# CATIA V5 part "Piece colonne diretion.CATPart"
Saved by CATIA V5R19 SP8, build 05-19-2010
Part number: Piece colonne diretion
Bounding box of the stored display mesh (mm): x -5.46 to 50.226, y -5.348 to 77.931, z -10 to 10
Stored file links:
  G:\EU_thinkMotion\CFAO_2010\MMS_groupe3\MMS_groupe3\A reprendre\lpastor\lpastor\Piece colonne diretion.CATPart
  C:\Users\Loïc\Documents\IFMA\Cours 2A\CFAO\Thinkmotion\Fourche avant.CATProduct
  G:\EU_thinkMotion\CFAO_2010\MMS_groupe3\MMS_groupe3\A reprendre\lpastor\lpastor\Pieces.CATProduct
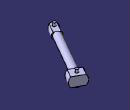
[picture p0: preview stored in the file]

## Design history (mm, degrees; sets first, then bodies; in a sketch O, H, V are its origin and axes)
External parameters (linked from other documents)
  External.Parametre_rayon_interieur_tube_cadre = 0.0045
Set1
  Plane1: linked copy from another document
  Line1 "Droite AB (colonne direction)": linked copy from another document
  Plane2 to Plane4: linked copy from another document
  Line2 "Droite B (colonne direction)": linked copy from another document
  Line3 "Droite A (colonne direction)": linked copy from another document
Body1 (main body)
  Sketch1 on Plane1, origin (36.0149, 62.7953, 0), H (0.8675, -0.4975, 0), V (0, 0, 1)
    circle A1 centre (0, 0) radius 4.5
    point P1 (0, 0)
    reference projected point E1 (0, 0) from Line1
    radius A1 = 4.5 {= External.Parametre_rayon_interieur_tube_cadre}
    coincidence: P1 E1
  Pad1: profile Sketch1, direction (-0.4975, -0.8675, 0), up to Plane2
  Sketch2 on Plane1, origin (36.0149, 62.7953, 0), H (0.8675, -0.4975, 0), V (0, 0, 1)
    arc A1 centre (0, 0) radius 9.5 from (-7.3655, 6) to (-9.5, 0) ccw
    point P1 (0, 0)
    reference projected point E1 (0, 0) from Line1
    line L1 (7.3655, 6) -> (-7.3655, 6)
    reference intersected line E2 through (0, 6) direction (-1, 0) from Plane3
    reference intersected line E3 through (0, 6) direction (-1, 0) from Plane3
    line L2 (9.5, 0) -> (-9.5, 0)
    reference projected point E4 (0, 0) from Line1
    arc A2 centre (0, 0) radius 9.5 from (9.5, 0) to (7.3655, 6) ccw
    radius A1 = 9.5
    coincidence: P1 E1, L1 E2, L2 E4, A1 A2
    horizontal: L1 H, L2 H
    parallelism: L1 E3
  Pad2: profile Sketch2, direction (0.4975, 0.8675, 0), length 12
  Sketch3 on Plane4, origin (0, 0, 4), H (1, 0, 0), V (0, 1, 0)
    line L1 (0.2041, 11.4109) -> (9.7461, 5.9383)
    line L2 (9.7461, 5.9383) -> (4.771, -2.7363)
    arc A1 centre (0, 0) radius 5.5 from (4.771, -2.7363) to (-4.771, 2.7363) cw
    point P4 (0, 0)
    line L3 (-4.771, 2.7363) -> (0.2041, 11.4109)
    reference intersected line E1 through (4.9751, 8.6746) direction (0.8675, -0.4975) from Plane2
    reference projected point E2 (0, 0) from Line2
    length L3 = 10
    length L1 = 11
    perpendicularity: L2 L1
    tangency: A1 L2, L3 A1
    coincidence: L1 E1, P4 E2
  Sketch4 on Plane2, origin (4.9751, 8.6746, 0), H (0.8675, -0.4975, 0), V (0, 0, 1)
    arc A1 centre (0, 0) radius 5.5 from (-3.7749, 4) to (-5.5, 0) ccw
    point P1 (0, 0)
    reference projected point E1 (0, 0) from Line1
    line L1 (-3.7749, 4) -> (3.7749, 4)
    line L2 (-5.5, 0) -> (5.5, 0)
    reference intersected line E2 through (0, 4) direction (-1, 0) from Plane4
    reference intersected line E3 through (0, 4) direction (-1, 0) from Plane4
    reference projected point E4 (0, 0) from Line1
    arc A2 centre (0, 0) radius 5.5 from (5.5, 0) to (3.7749, 4) ccw
    radius A1 = 5.5
    coincidence: P1 E1, L1 E2, L2 E4, A1 A2
    horizontal: L1 H, L2 H
    parallelism: L1 E3
  SolidCombine1: FirstComponentProfile Sketch3, FirstComponentDirection Sketch3, SecondComponentProfile Sketch4, SecondComponentDirection Sketch4
  Sketch5 on Plane4, origin (0, 0, 4), H (1, 0, 0), V (0, 1, 0)
    circle A1 centre (0, 0) radius 2
    point P1 (0, 0)
    reference projected point E1 (0, 0) from Line2
    radius A1 = 2
    coincidence: P1 E1
  Pad3: profile Sketch5, direction (0, 0, 1), length 4
  Sketch6 on Plane3, origin (0, 0, 6), H (1, 0, 0), V (0, 1, 0)
    circle A1 centre (39, 68) radius 2
    point P1 (39, 68)
    reference projected point E1 (39, 68) from Line3
    radius A1 = 2
    coincidence: P1 E1
  Pad4: profile Sketch6, direction (0, 0, 1), length 4
  Mirror1: of Pad2, Pad4, about face of Pad2 from Sketch2.L2
  Mirror2: of SolidCombine1, Pad3, about face of SolidCombine1 from Sketch4.L2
